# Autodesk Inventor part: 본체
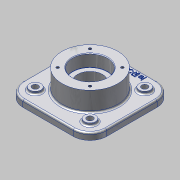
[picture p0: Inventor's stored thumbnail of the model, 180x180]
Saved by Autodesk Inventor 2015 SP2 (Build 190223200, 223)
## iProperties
Created: 2015-07
Part Number: 본체
Material: 알루미늄 6061
Document SubType Name: Modeling
Designer: AMC
Density: 2.7 g/cm^3
Appearance: 알루미늄 - 평지
Mass: 1457.61 g
Surface Area: 804.939 cm^2
Volume: 539.856 cm^3
Author: AMC
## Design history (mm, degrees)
sketch "스케치1"
  geometry: L1 (-75, -75)-(75, -75); L2 (75, -75)-(75, 75); L3 (75, 75)-(-75, 75); L4 (-75, 75)-(-75, -75); L5 (-75, -75)-(75, 75); L6 (75, -75)-(-75, 75); 1 further point
  constraints: 12 end point, 2 midpoint, 2 parallel, 1 horizontal, 1 perpendicular
  dimensions: "d0" = 150 distance of L3.end L2.end; "d1" = 150 distance of L2.end L1.end
extrude "돌출1" new body sketch "스케치1" distance "d2" = 12; taper "d3" = 0 deg
sketch "스케치2"
  geometry: C1 r 50 at (0, 0); 1 further point
  constraints: 1 centre point, 1 coincident
  dimensions: "d4" = 100 diameter of C1
extrude "돌출2" join sketch "스케치2" distance "d5" = 47; taper "d7" = 0 deg; dims "d6" = 23, "d8" = 0
hole "구멍1" diameter "d11" = 45; stored, may be unused: countersink angle "d15" = 90 deg, drill point angle "d17" = 0 deg; dims "d12" = 6, "d13" = 62, "d14" = 22, "d16" = 8, "d111" = 10, "d112" = 10
hole "구멍2" diameter "d22" = 62; stored, may be unused: countersink angle "d26" = 90 deg, drill point angle "d28" = 0 deg; dims "d23" = 6, "d24" = 62, "d25" = 22, "d27" = 22, "d113" = 10, "d114" = 10
sketch "스케치3"
  geometry: L1 (-49, -49)-(49, -49); L2 (49, -49)-(49, 49); L3 (49, 49)-(-49, 49); L4 (-49, 49)-(-49, -49); L5 (-49, -49)-(49, 49); L6 (49, -49)-(-49, 49); C1 r 10 at (-49, 49); C2 r 10 at (49, 49); C3 r 10 at (-49, -49); C4 r 10 at (49, -49); 1 further point
  constraints: 12 end point, 4 centre point, 4 coincident, 2 midpoint, 2 parallel, 1 horizontal, 1 perpendicular
  dimensions: "d29" = 98 distance of L3.end L2.end; "d30" = 98 distance of L2.end L1.end; "d31" = 20 diameter of C1; "d32" = 20 diameter of C2; "d33" = 20 diameter of C3; "d34" = 20 diameter of C4
extrude "돌출3" join sketch "스케치3" distance "d35" = 5; taper "d36" = 0 deg
hole "구멍3" diameter "d39" = 11; stored, may be unused: countersink angle "d43" = 90 deg, drill point angle "d45" = 118 deg; dims "d37" = 10, "d38" = 10, "d40" = 6, "d41" = 62, "d42" = 22, "d44" = 22
hole "구멍4" diameter "d48" = 11; stored, may be unused: countersink angle "d52" = 90 deg, drill point angle "d54" = 118 deg; dims "d46" = 10, "d47" = 10, "d49" = 6, "d50" = 62, "d51" = 22, "d53" = 22
hole "구멍5" diameter "d57" = 11; stored, may be unused: countersink angle "d61" = 90 deg, drill point angle "d63" = 118 deg; dims "d55" = 10, "d56" = 10, "d58" = 6, "d59" = 62, "d60" = 22, "d62" = 22
hole "구멍6" diameter "d66" = 11; stored, may be unused: countersink angle "d70" = 90 deg, drill point angle "d72" = 118 deg; dims "d64" = 10, "d65" = 10, "d67" = 6, "d68" = 62, "d69" = 22, "d71" = 22
sketch "스케치4"
  geometry: L1 (0, 0)-(28.991, 28.991); L2 (0, 0)-(41, 0); C1 r 41 at (0, 0); 2 further points
  constraints: 4 end point, 2 coincident, 1 centre point, 1 equal length, 1 horizontal
  dimensions: "d73" = 82 diameter of C1; "d74" = 41 distance of L1.start L1.end; "d75" = 45 deg angle of L2 L1
hole "구멍7" sketch "스케치4" at (28.991, 28.991) diameter "d76" = 4.917; stored, may be unused: countersink angle "d80" = 90 deg, drill point angle "d82" = 118 deg; dims "d77" = 10, "d78" = 62, "d79" = 22, "d81" = 13
sketch "스케치5"
  geometry: L1 (0, 0)-(28.991, 28.991); L2 (0, 0)-(41, 0); C1 r 41 at (0, 0); 2 further points
  constraints: 4 end point, 2 coincident, 1 centre point, 1 equal length, 1 horizontal
  dimensions: "d86" = 82 diameter of C1; "d87" = 41 distance of L1.start L1.end; "d88" = 45 deg angle of L2 L1
hole "구멍8" sketch "스케치5" at (28.991, 28.991) diameter "d89" = 4.917; stored, may be unused: countersink angle "d93" = 90 deg, drill point angle "d95" = 118 deg; dims "d90" = 10, "d91" = 62, "d92" = 22, "d94" = 13
fillet "모깎기1" dims "d99" = 3
fillet "모깎기2" dims "d100" = 0.3
chamfer "모따기1" distance "d101" = 1; stored, may be unused: second distance "d102" = 2, angle "d103" = 45 deg
fillet "모깎기3" dims "d104" = 30
sketch "스케치7"
  geometry: 2 further points
  constraints: 1 other
  dimensions: "d108" = 65 vertical distance of point (0, 0) point (0.255, 65)
feature "엠보싱2" sketch "스케치7" dims "d0" = 150, "d1" = 150, "d29" = 98, "d30" = 98, "d31" = 20, "d32" = 20, "d33" = 20, "d34" = 20, "d109" = 1, "d110" = 0
node "솔리드1"
pattern_circular "원형 패턴3" dims angle "d116" = 360 deg
pattern_circular "원형 패턴4" dims angle "d119" = 360 deg
